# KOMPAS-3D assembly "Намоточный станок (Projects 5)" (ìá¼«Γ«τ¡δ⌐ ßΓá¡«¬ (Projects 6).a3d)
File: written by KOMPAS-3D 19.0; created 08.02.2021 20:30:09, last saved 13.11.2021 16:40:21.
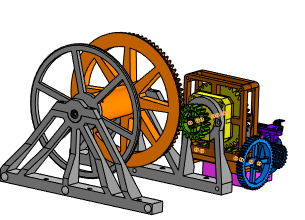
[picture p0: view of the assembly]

Document properties: Автор: Agent Smith; Полное имя файла: D:\3D_print\3D проекты Компас 3D\Редуктор (Снова)\Намоточный станок (Projects 6).a3d

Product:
- Part/product: Намоточный станок (Projects 5)
    Материал: АБС 0603Т ТУ 2214-019-002 03521-96 (density 0 kg/m3)
    Масса: 1.49155
  - Component [assembly]: Reductor  | designation R-10  | Материал: АБС 0603Т ТУ 2214-019-002 03521-96 (density 0 kg/m3); Масса: 0.009492; source file: R-10 - Reductor.a3d
  - Component [detail]: Ведущая щестерня под Редуктор  | Материал: АБС 0603Т ТУ 2214-019-002 03521-96 (density 0 kg/m3); source file: Ведущая щестерня под Редуктор(Снова).m3d
  - Component [detail]: Крышка_подшипника  | qty 2  | Масса: 0.0173967; source file: ..\Халява Projects 5\Крышка_подшипника.m3d
  - Component [detail]: Рама_вспомогательная  | Масса: 0.367054; source file: ..\Халява Projects 5\Рама_вспомогательная .m3d
  - Component [detail]: Подшипник  | qty 2  | Материал: Сталь ШХ-10 ГОСТ 808-70 (density 7850 kg/m3); Масса: 0.00697738; source file: ..\Халява Projects_3\Подшипник.m3d
  - Component [detail]: Втулка_намоточного  | qty 2  | Материал: Полиэтилен 20108-001 ГОСТ 16338-85 (density 949 kg/m3); Масса: 0.00235951; source file: ..\Халява Projects 5\Втулка_намоточного.m3d
  - Component [detail]: Vedom_Krugl  | Материал: Полиэтилен 20108-001 ГОСТ 16338-85 (density 949 kg/m3); Масса: 0.0174592; source file: ..\Халява Projects\Vedom_Krugl.m3d
  - Component [detail]: Vedom_koleso  | Материал: Полиэтилен 20108-001 ГОСТ 16338-85 (density 949 kg/m3); Масса: 0.0863366; source file: ..\Халява Projects\Vedom_koleso.m3d
  - Component [detail]: Рама_основная  | Масса: 0.415808; source file: ..\Халява Projects 5\Рама_основная.m3d
  - Component [detail]: Переходник на Nema_17  | Масса: 0.0956301; source file: ..\Халява Projects 5\Переходник на Nema_17.m3d
  - Component [detail]: Motor_D36x50  | Масса: 0.403081; source file: Motor_D36x50.m3d
  - Component [standard]: Шайба A.3.37 ГОСТ 11371-78  | qty 5  | Материал: АД1 ГОСТ 4784-97 (density 1000 kg/m3); Масса: 0.000119; Раздел спецификации: Стандартные изделия; Рассекать на разрезах: no; source file: C:\Program Files\ASCON\KOMPAS-3D v19\Libs\PARTLib\DATA\vault\Methods\Kompas\3D\PLib_Washer_1_712.m3d
  - Component [standard]: Гайка М3-6H ГОСТ 5915-70  | qty 5  | Масса: 0.000377; Раздел спецификации: Стандартные изделия; Рассекать на разрезах: no; source file: C:\Program Files\ASCON\KOMPAS-3D v19\Libs\PARTLib\DATA\vault\Methods\Kompas\3D\PLib_Nut_OST92_900.m3d
  - Component [detail]: Зуб.колесо выход на редуктор  | Материал: АБС 0603Т ТУ 2214-019-002 03521-96 (density 0 kg/m3); source file: Вход на редуктор.m3d
  - Component [detail]: Шестерня на мотор Z-20  | Материал: АБС 0603Т ТУ 2214-019-002 03521-96 (density 0 kg/m3); source file: Шестерня на мотор Z-20.m3d
  - Component [detail]: Держатель мотора 36мм  | Материал: АБС 0603Т ТУ 2214-019-002 03521-96 (density 0 kg/m3); source file: Держатель мотора 36мм.m3d
  - Component [detail]: Щелевой оптический датчик  | Материал: Полиэтилен 20108-001 ГОСТ 16338-85 (density 949 kg/m3); Масса: 0.00128443; source file: Щелевой оптический датчик.m3d
  - Component [detail]: Крышка мотора  | Масса: 0.020193; source file: Крышка мотора.m3d
  - Component [detail]: Крышка мотора 2  | Масса: 0.0176424; source file: Крышка мотора 2.m3d
  - Component [detail]: Переходник на Редуктор  | Материал: АБС 0603Т ТУ 2214-019-002 03521-96 (density 0 kg/m3); source file: Переходник Редуктор.m3d
  - Component [standard]: Подшипник 23 ГОСТ 8338-75  | Масса: 0.0015; Раздел спецификации: Стандартные изделия; Рассекать на разрезах: no; additional columns: 23; source file: C:\Program Files\ASCON\KOMPAS-3D v19\Libs\PARTLib\DATA\vault\Methods\Kompas\3D\Bearings\8338_75\PLib_Bearing_GOST_8338_75_712.a3d

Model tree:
1. Эскиз:2  (with: Цилиндр (Шестерня цилиндрическая с внешними зубьями):1)
2. Эскиз:3  (with: Элемент выдавливания:1, Элемент выдавливания:2, Скругление:1, Элемент выдавливания:7, Цилиндр (Шестерня цилиндрическая с внешними зубьями):1, Элемент выдавливания:3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)  (labels: Фаска:3; Фаска:3; Фаска:3; Фаска:3)
     Ориентация = 2; Ориентация = 2; Ориентация = 2; Ориентация = 2; Ориентация = 2; Ориентация = 2; Ориентация = 2

Referenced files in D:\3D_print\3D проекты Компас 3D\Халява Projects\: Vedom_koleso.m3d, Vedom_Krugl.m3d
Referenced files in D:\3D_print\3D проекты Компас 3D\Халява Projects_3\: Подшипник.m3d
Referenced files in D:\3D_print\3D проекты Компас 3D\Халява Projects 5\: Рама_вспомогательная .m3d, Втулка_намоточного.m3d, Крышка_подшипника.m3d, Переходник на Nema_17.m3d, Рама_основная.m3d
Referenced files in D:\3D_print\3D проекты Компас 3D\Редуктор (Снова)\: Ведущая щестерня под Редуктор(Снова).m3d, R-10 - Reductor.a3d, Motor_D36x50.m3d, Вход на редуктор.m3d, Шестерня на мотор Z-20.m3d, Держатель мотора 36мм.m3d, Крышка мотора.m3d, Щелевой оптический датчик.m3d, Крышка мотора 2.m3d, Переходник Редуктор.m3d
Referenced files: SPDS_GR_2014.LYT, SPDS.tdp
Referenced files in C:\Program Files\ASCON\KOMPAS-3D v19\Libs\PARTLib\DATA\vault\Methods\Kompas\3D\: PLib_Washer_1_712.m3d, PLib_Nut_OST92_900.m3d
Referenced files in C:\Program Files\ASCON\KOMPAS-3D v19\Libs\PARTLib\DATA\vault\Methods\Kompas\3D\Bearings\8338_75\: PLib_Bearing_GOST_8338_75_712.a3d
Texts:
  01 Спецификация. ГОСТ Р 21.1101-2013 Ф7
  Втулка_намоточного (1)
  Втулка_намоточного (2)
  Подшипник (1)
  Подшипник (2)
  Крышка_подшипника (1)
  Крышка_подшипника (2)
  R-10 Reductor
  Шайба A.3.37 ГОСТ 11371-78 (1)
  Гайка М3-6H ГОСТ 5915-70 (1)
  bcut1
  hole1
  hcut1
  hole2
  cut1
  Шайба A.3.37 ГОСТ 11371-78 (2)
  Шайба A.3.37 ГОСТ 11371-78 (3)
  Гайка М3-6H ГОСТ 5915-70 (2)
  Шайба A.3.37 ГОСТ 11371-78 (4)
  Гайка М3-6H ГОСТ 5915-70 (3)
  Шайба A.3.37 ГОСТ 11371-78 (5)
  Гайка М3-6H ГОСТ 5915-70 (4)
  Шайба A.3.37 ГОСТ 11371-78 (6)
  Гайка М3-6H ГОСТ 5915-70 (5)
